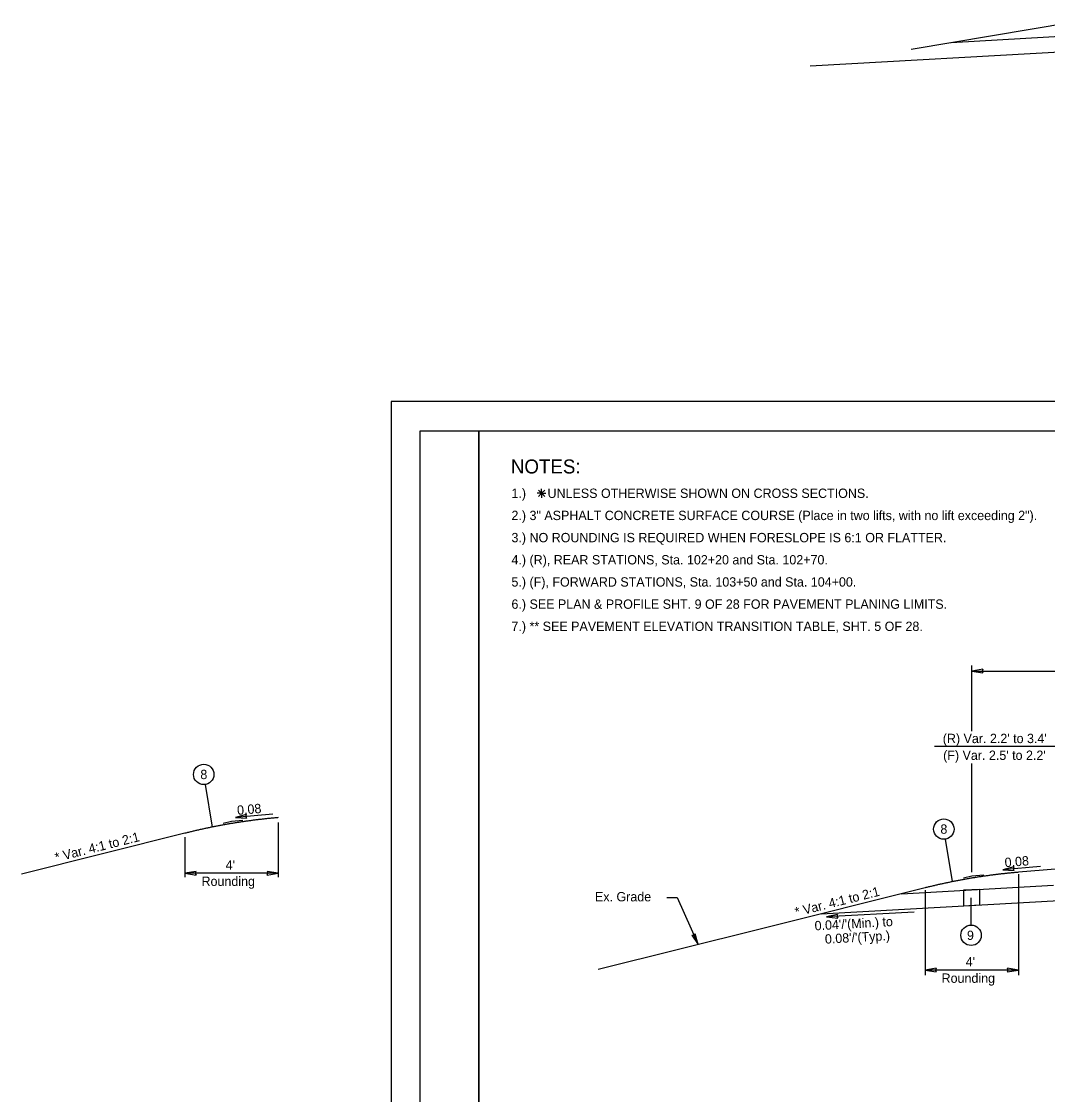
# Model space of a CAD drawing. Extents: x -32 to 684, y -204 to 158.
# Drawn here: x -31.7 to 56.2, y 50.6 to 142.6 of the extents above; entities that cross this region are included whole.
import ezdxf

# ---------------------------------------------------------------- set-up
doc = ezdxf.new("R2010")
doc.units = 0
for name, color, linetype in [('Level 1', 7, 'Continuous'), ('PV_X_Shoulder', 7, 'Continuous'), ('SH_Data', 7, 'Continuous'), ('XS_X_Pavt', 7, 'Continuous')]:
    doc.layers.add(name, color=color, linetype=linetype)

msp = doc.modelspace()

# ---------------------------------------------------------------- linework, layer by layer
at = {"layer": 'Level 1'}
for points in [[(49.755, 86.908), (49.753, 86.905)], [(49.757, 86.907), (49.753, 86.905)], [(-13.342, 74.369), (-13.344, 74.366)], [(-13.34, 74.368), (-13.343, 74.366)], [(52.434, 69.887), (52.432, 69.885)], [(52.436, 69.887), (52.433, 69.885)], [(-17.664, 69.586), (-17.667, 69.583)], [(-17.663, 69.585), (-17.666, 69.583)], [(-9.676, 69.583), (-9.673, 69.585)], [(-9.675, 69.582), (-9.672, 69.585)], [(37.324, 65.836), (37.321, 65.833)], [(37.326, 65.835), (37.322, 65.833)], [(26.295, 63.471), (26.298, 63.468)], [(26.295, 63.469), (26.299, 63.468)], [(45.755, 61.286), (45.753, 61.283)], [(45.757, 61.285), (45.753, 61.283)], [(53.743, 61.283), (53.747, 61.285)], [(53.745, 61.282), (53.747, 61.285)]]:
    msp.add_lwpolyline(points, dxfattribs=at)
at = {"layer": 'PV_X_Shoulder'}
for points in [[(2.5, 107.5), (7.5, 107.5), (7.5, 2.5), (2.5, 2.5)], [(7.5, 107.5), (167.5, 107.5), (167.5, 2.5), (7.5, 2.5)]]:
    msp.add_lwpolyline(points, close=True, dxfattribs=at)
at = {"layer": 'SH_Data'}
for p, q in [((44.572, 140.207), (58.753, 142.571)), ((47.982, 140.775), (64.753, 141.715)), ((35.914, 138.764), (65.753, 140.435)), ((12.893, 102.138), (12.518, 102.138)), ((12.893, 102.138), (12.627, 102.404)), ((12.893, 102.138), (12.627, 101.873)), ((12.893, 102.138), (12.893, 102.513)), ((12.893, 102.138), (13.158, 102.404)), ((12.893, 102.138), (13.268, 102.138)), ((12.893, 102.138), (13.158, 101.873)), ((12.893, 102.138), (12.893, 101.763)), ((49.75, 81.769), (49.75, 87.371)), ((50.7, 87.064), (49.75, 86.906)), ((49.75, 86.906), (83.75, 86.906)), ((49.75, 86.906), (50.697, 86.748)), ((50.697, 86.748), (50.697, 86.748)), ((58.75, 80.433), (46.562, 80.433)), ((49.75, 69.683), (49.75, 78.979)), ((-15.31, 73.542), (-15.917, 77.185)), ((-10.14, 74.635), (-13.347, 74.366)), ((-12.413, 74.603), (-13.347, 74.366)), ((-13.67, 74.01), (-14.385, 73.831)), ((-12.717, 74.09), (-13.67, 74.01)), ((-13.347, 74.366), (-12.39, 74.288)), ((-12.39, 74.288), (-12.39, 74.288)), ((-9.67, 73.939), (-9.67, 69.259)), ((-17.67, 73.01), (-31.681, 69.507)), ((-17.67, 72.66), (-17.67, 69.259)), ((48.11, 68.86), (47.502, 72.503)), ((55.636, 70.153), (52.429, 69.885)), ((53.363, 70.122), (52.429, 69.885)), ((52.429, 69.885), (53.386, 69.806)), ((58.75, 70.081), (53.75, 69.663)), ((-16.72, 69.742), (-17.67, 69.584)), ((-17.67, 69.584), (-16.723, 69.426)), ((-9.67, 69.584), (-17.67, 69.584)), ((-16.723, 69.426), (-16.723, 69.426)), ((-10.619, 69.426), (-9.67, 69.584)), ((-9.67, 69.584), (-10.616, 69.742)), ((-10.616, 69.742), (-10.616, 69.742)), ((49.75, 69.328), (49.035, 69.149)), ((50.792, 69.415), (49.75, 69.328)), ((53.386, 69.806), (53.386, 69.806)), ((53.75, 69.504), (53.75, 60.851)), ((45.75, 68.328), (31.739, 64.825)), ((43.742, 67.826), (56.75, 68.554)), ((45.75, 68.133), (45.75, 60.851)), ((23.618, 67.507), (24.519, 67.507)), ((24.519, 67.507), (26.299, 63.465)), ((36.858, 66.105), (57.75, 67.275)), ((49.695, 65.14), (49.695, 67.481)), ((44.832, 66.254), (37.319, 65.834)), ((38.255, 66.056), (37.319, 65.834)), ((37.319, 65.834), (38.274, 65.741)), ((38.274, 65.741), (38.274, 65.741)), ((31.739, 64.825), (17.728, 61.322)), ((26.299, 63.465), (26.059, 64.394)), ((26.059, 64.394), (26.059, 64.394)), ((25.769, 64.269), (26.299, 63.465)), ((46.7, 61.442), (45.75, 61.284)), ((45.75, 61.284), (46.697, 61.126)), ((53.75, 61.284), (45.75, 61.284)), ((46.697, 61.126), (46.697, 61.126)), ((52.8, 61.126), (53.75, 61.284)), ((53.75, 61.284), (52.803, 61.442)), ((52.803, 61.442), (52.803, 61.442))]:
    msp.add_line(p, q, dxfattribs=at)
msp.add_lwpolyline([(50.436, 68.2), (49.036, 68.122), (49.036, 66.787), (50.436, 66.865)], close=True, dxfattribs=at)
for centre in [(-16.061, 78.048), (47.359, 73.366), (49.695, 64.265)]:
    msp.add_circle(centre, 0.875, dxfattribs=at)
for centre, start, end in [((50.939, 86.904), 146.178, 212.85877), ((-12.162, 74.463), 150.96101, 217.64177), ((53.614, 69.982), 150.96101, 217.64177), ((-16.481, 69.582), 146.178, 212.85877), ((-10.858, 69.586), 326.178, 32.85877), ((38.505, 65.913), 150.09088, 216.77164), ((25.818, 64.552), 260.14385, 326.82462), ((46.939, 61.282), 146.178, 212.85877), ((52.561, 61.286), 326.178, 32.85877)]:
    msp.add_arc(centre, 0.288, start, end, dxfattribs=at)
for points in [[(-9.67, 74.345), (-9.823, 74.332), (-9.977, 74.318), (-10.131, 74.304), (-10.285, 74.289), (-10.439, 74.274), (-10.593, 74.259), (-10.746, 74.243), (-10.9, 74.226), (-11.054, 74.209), (-11.208, 74.191), (-11.362, 74.173), (-11.516, 74.155), (-11.67, 74.136), (-11.823, 74.116), (-11.977, 74.096), (-12.131, 74.076), (-12.285, 74.055), (-12.439, 74.033), (-12.593, 74.011), (-12.746, 73.989), (-12.9, 73.966), (-13.054, 73.942), (-13.208, 73.918), (-13.362, 73.894), (-13.516, 73.869), (-13.67, 73.844), (-13.823, 73.818), (-13.977, 73.791), (-14.131, 73.764), (-14.285, 73.737), (-14.439, 73.709), (-14.593, 73.681), (-14.746, 73.652), (-14.9, 73.623), (-15.054, 73.593), (-15.208, 73.562), (-15.362, 73.532), (-15.516, 73.5), (-15.67, 73.468), (-15.823, 73.436), (-15.977, 73.403), (-16.131, 73.37), (-16.285, 73.336), (-16.439, 73.302), (-16.593, 73.267), (-16.746, 73.232), (-16.9, 73.196), (-17.054, 73.16), (-17.208, 73.123), (-17.362, 73.086), (-17.516, 73.048), (-17.67, 73.01)], [(53.75, 69.663), (53.596, 69.649), (53.442, 69.636), (53.288, 69.622), (53.135, 69.607), (52.981, 69.592), (52.827, 69.576), (52.673, 69.56), (52.519, 69.544), (52.365, 69.527), (52.212, 69.509), (52.058, 69.491), (51.904, 69.473), (51.75, 69.454), (51.596, 69.434), (51.442, 69.414), (51.288, 69.393), (51.135, 69.372), (50.981, 69.351), (50.827, 69.329), (50.673, 69.307), (50.519, 69.284), (50.365, 69.26), (50.212, 69.236), (50.058, 69.212), (49.904, 69.187), (49.75, 69.161), (49.596, 69.135), (49.442, 69.109), (49.288, 69.082), (49.135, 69.055), (48.981, 69.027), (48.827, 68.998), (48.673, 68.97), (48.519, 68.94), (48.365, 68.91), (48.212, 68.88), (48.058, 68.849), (47.904, 68.818), (47.75, 68.786), (47.596, 68.754), (47.442, 68.721), (47.288, 68.688), (47.135, 68.654), (46.981, 68.62), (46.827, 68.585), (46.673, 68.549), (46.519, 68.514), (46.365, 68.477), (46.212, 68.441), (46.058, 68.404), (45.904, 68.366), (45.75, 68.328)]]:
    msp.add_spline(points, degree=3, dxfattribs=at)
at = {"layer": 'XS_X_Pavt'}
msp.add_lwpolyline([(0, 0), (170, 0), (170, 110), (0, 110)], close=True, dxfattribs=at)

# ---------------------------------------------------------------- texts
at = {"layer": 'SH_Data'}
for s, height, p in [('NOTES:', 1.2, (10.258, 103.837)), ('1.)    - UNLESS OTHERWISE SHOWN ON CROSS SECTIONS.', 0.8, (10.31, 101.743)), ('2.) 3" ASPHALT CONCRETE SURFACE COURSE (Place in two lifts, with no lift exceeding 2").', 0.8, (10.31, 99.843)), ('3.) NO ROUNDING IS REQUIRED WHEN FORESLOPE IS 6:1 OR FLATTER.', 0.8, (10.31, 97.943)), ('4.) (R), REAR STATIONS, Sta. 102+20 and Sta. 102+70.', 0.8, (10.31, 96.043)), ('5.) (F), FORWARD STATIONS, Sta. 103+50 and Sta. 104+00.', 0.8, (10.31, 94.143)), ('6.) SEE PLAN & PROFILE SHT. 9 OF 28 FOR PAVEMENT PLANING LIMITS.', 0.8, (10.31, 92.243)), ('7.) ** SEE PAVEMENT ELEVATION TRANSITION TABLE, SHT. 5 OF 28.', 0.8, (10.31, 90.343)), ("(R) Var. 2.2' to 3.4'", 0.8, (47.27, 80.732)), ("(F) Var. 2.5' to 2.2'", 0.8, (47.303, 79.292)), ('8', 0.8, (-16.351, 77.648)), ('8', 0.8, (47.069, 72.966)), ("4'", 0.8, (-14.184, 69.892)), ('Rounding', 0.8, (-16.25, 68.492)), ('Ex. Grade', 0.8, (17.465, 67.171)), ('9', 0.8, (49.345, 63.864)), ("4'", 0.8, (49.235, 61.592)), ('Rounding', 0.8, (47.169, 60.192))]:
    msp.add_text(s, height=height, dxfattribs=at).set_placement(p)
for s, rotation, p in [('0.08', 4.78301, (-13.17, 74.577)), ('* Var. 4:1 to 2:1', 14.03624, (-28.708, 70.544)), ('0.08', 4.78301, (52.606, 70.096)), ('* Var. 4:1 to 2:1', 14.03624, (34.712, 65.862)), ("0.04'/'(Min.) to", 3.20567, (36.311, 64.683)), ("0.08'/'(Typ.)", 3.20567, (37.192, 63.54))]:
    msp.add_text(s, height=0.8, rotation=rotation, dxfattribs=at).set_placement(p)

doc.saveas('drawing.dxf')
